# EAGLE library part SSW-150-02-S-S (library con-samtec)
THROUGH-HOLE .025" SQ POST SOCKET Source: Samtec SSW.pdf
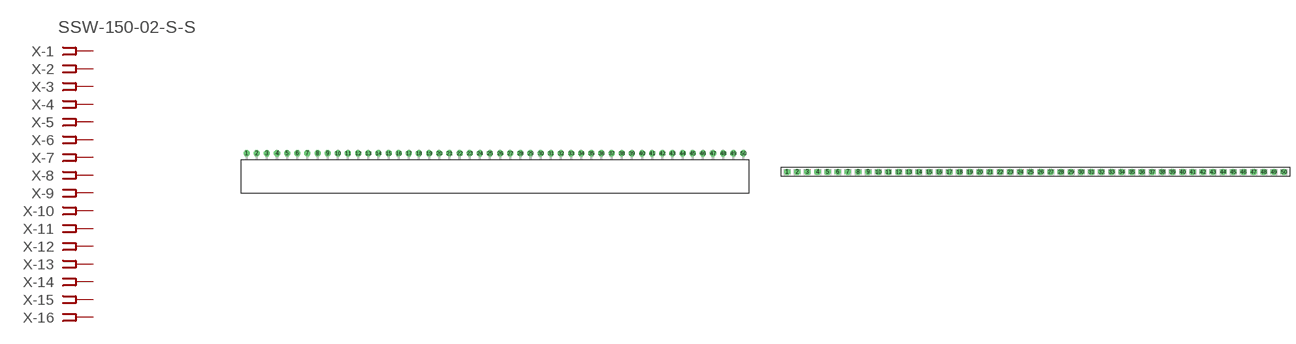
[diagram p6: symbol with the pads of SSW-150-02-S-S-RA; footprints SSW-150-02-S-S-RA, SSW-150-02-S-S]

Designator prefix X; gates -1=FPINV -2=FPIN -3=FPIN -4=FPIN -5=FPIN -6=FPIN -7=FPIN -8=FPIN -9=FPIN -10=FPIN -11=FPIN -12=FPIN -13=FPIN -14=FPIN -15=FPIN -16=FPIN -17=FPIN -18=FPIN -19=FPIN -20=FPIN -21=FPIN -22=FPIN -23=FPIN -24=FPIN -25=FPIN -26=FPIN -27=FPIN -28=FPIN -29=FPIN -30=FPIN -31=FPIN -32=FPIN -33=FPIN -34=FPIN -35=FPIN -36=FPIN -37=FPIN -38=FPIN -39=FPIN -40=FPIN -41=FPIN -42=FPIN -43=FPIN -44=FPIN -45=FPIN -46=FPIN -47=FPIN -48=FPIN -49=FPIN -50=FPIN

## SSW-150-02-S-S-RA (MPN: SSW-150-02-S-S-RA; OC_FARNELL: unknown; OC_NEWARK: 12P0074)  [SSW-150-02-S-S-RA]
1  -1:1  pas
2  -2:1  pas
3  -3:1  pas
4  -4:1  pas
5  -5:1  pas
6  -6:1  pas
7  -7:1  pas
8  -8:1  pas
9  -9:1  pas
10  -10:1  pas
11  -11:1  pas
12  -12:1  pas
13  -13:1  pas
14  -14:1  pas
15  -15:1  pas
16  -16:1  pas
17  -17:1  pas
18  -18:1  pas
19  -19:1  pas
20  -20:1  pas
21  -21:1  pas
22  -22:1  pas
23  -23:1  pas
24  -24:1  pas
25  -25:1  pas
26  -26:1  pas
27  -27:1  pas
28  -28:1  pas
29  -29:1  pas
30  -30:1  pas
31  -31:1  pas
32  -32:1  pas
33  -33:1  pas
34  -34:1  pas
35  -35:1  pas
36  -36:1  pas
37  -37:1  pas
38  -38:1  pas
39  -39:1  pas
40  -40:1  pas
41  -41:1  pas
42  -42:1  pas
43  -43:1  pas
44  -44:1  pas
45  -45:1  pas
46  -46:1  pas
47  -47:1  pas
48  -48:1  pas
49  -49:1  pas
50  -50:1  pas

## SSW-150-02-S-S (MPN: SSW-150-02-S-S; OC_FARNELL: unknown; OC_NEWARK: 12P0073)  [SSW-150-02-S-S]
Pads as for SSW-150-02-S-S-RA

## Footprint SSW-150-02-S-S-RA (pad centres in mm)
THROUGH-HOLE .025" SQ POST SOCKET Source: Samtec SSW.pdf
drill 1 pad 1.5 octagon: 1 -62.23,1.524; 2 -59.69,1.524; 3 -57.15,1.524; 4 -54.61,1.524; 5 -52.07,1.524; 6 -49.53,1.524; 7 -46.99,1.524; 8 -44.45,1.524; 9 -41.91,1.524; 10 -39.37,1.524; 11 -36.83,1.524; 12 -34.29,1.524; 13 -31.75,1.524; 14 -29.21,1.524; 15 -26.67,1.524; 16 -24.13,1.524; 17 -21.59,1.524; 18 -19.05,1.524; 19 -16.51,1.524; 20 -13.97,1.524; 21 -11.43,1.524; 22 -8.89,1.524; 23 -6.35,1.524; 24 -3.81,1.524; 25 -1.27,1.524; 26 1.27,1.524; 27 3.81,1.524; 28 6.35,1.524; 29 8.89,1.524; 30 11.43,1.524; 31 13.97,1.524; 32 16.51,1.524; 33 19.05,1.524; 34 21.59,1.524; 35 24.13,1.524; 36 26.67,1.524; 37 29.21,1.524; 38 31.75,1.524; 39 34.29,1.524; 40 36.83,1.524; 41 39.37,1.524; 42 41.91,1.524; 43 44.45,1.524; 44 46.99,1.524; 45 49.53,1.524; 46 52.07,1.524; 47 54.61,1.524; 48 57.15,1.524; 49 59.69,1.524; 50 62.23,1.524

## Footprint SSW-150-02-S-S (pad centres in mm)
THROUGH-HOLE .025" SQ POST SOCKET Source: Samtec SSW.pdf
drill 1 pad 1.5 octagon: 1 -62.23,0; 2 -59.69,0; 3 -57.15,0; 4 -54.61,0; 5 -52.07,0; 6 -49.53,0; 7 -46.99,0; 8 -44.45,0; 9 -41.91,0; 10 -39.37,0; 11 -36.83,0; 12 -34.29,0; 13 -31.75,0; 14 -29.21,0; 15 -26.67,0; 16 -24.13,0; 17 -21.59,0; 18 -19.05,0; 19 -16.51,0; 20 -13.97,0; 21 -11.43,0; 22 -8.89,0; 23 -6.35,0; 24 -3.81,0; 25 -1.27,0; 26 1.27,0; 27 3.81,0; 28 6.35,0; 29 8.89,0; 30 11.43,0; 31 13.97,0; 32 16.51,0; 33 19.05,0; 34 21.59,0; 35 24.13,0; 36 26.67,0; 37 29.21,0; 38 31.75,0; 39 34.29,0; 40 36.83,0; 41 39.37,0; 42 41.91,0; 43 44.45,0; 44 46.99,0; 45 49.53,0; 46 52.07,0; 47 54.61,0; 48 57.15,0; 49 59.69,0; 50 62.23,0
